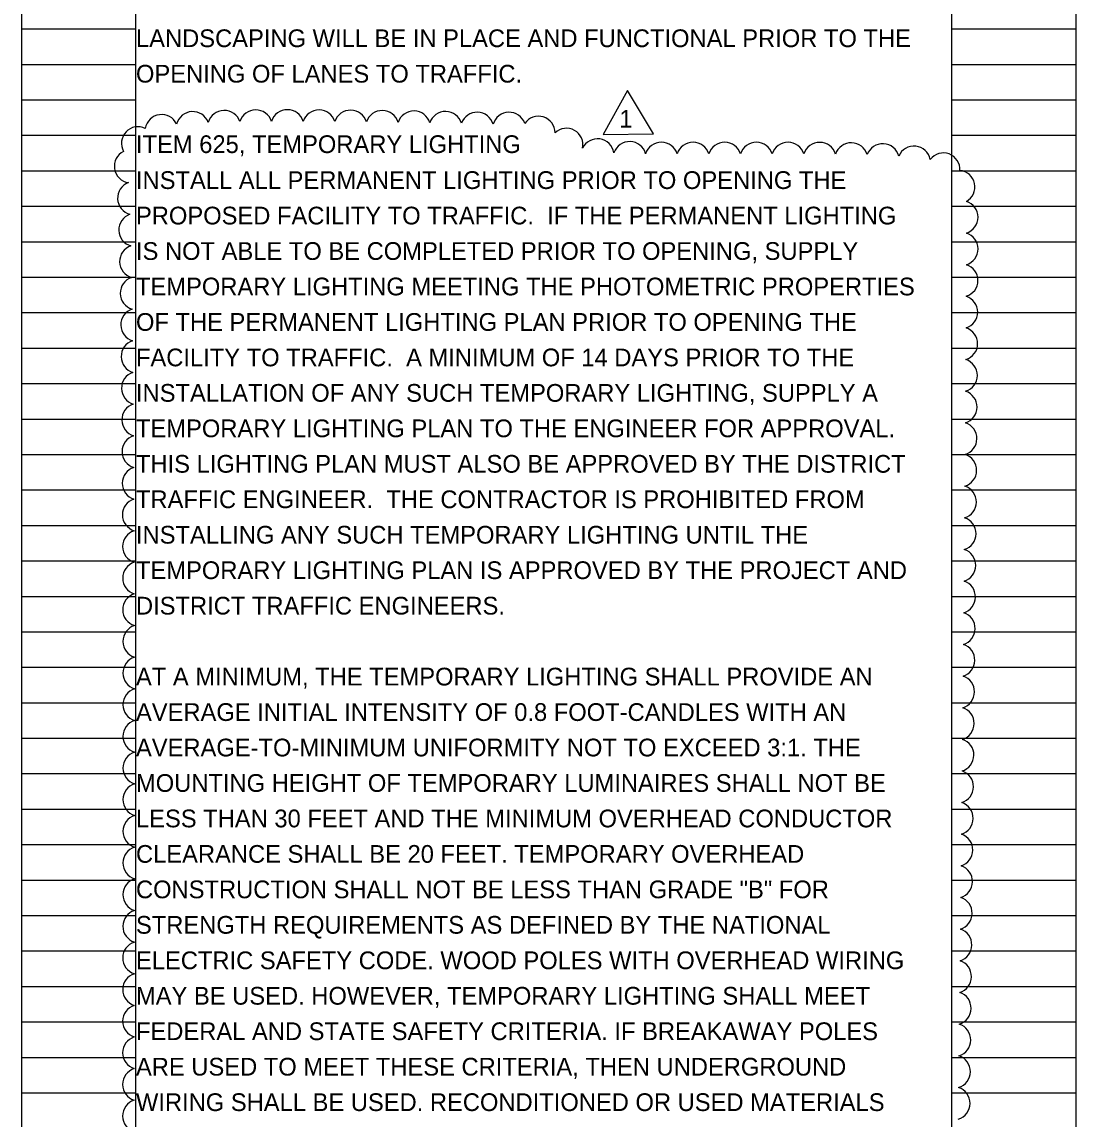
# Model space of a CAD drawing. Extents: x -9 to 32, y -122 to 20.
# Drawn here: x 1.22 to 9.54, y -94.82 to -86.16 of the extents above; entities that cross this region are included whole.
import ezdxf

# ---------------------------------------------------------------- set-up
doc = ezdxf.new("R2010")
doc.units = 0
for name, color, linetype in [('SC_Scratch1', 7, 'Continuous'), ('SC_Scratch2', 7, 'Continuous'), ('SH_Text', 7, 'Continuous')]:
    doc.layers.add(name, color=color, linetype=linetype)

msp = doc.modelspace()

# ---------------------------------------------------------------- linework, layer by layer
at = {"layer": 'SC_Scratch1'}
for p, q in [((1.2158, -100.4944), (1.2158, -80.3344)), ((2.1158, -100.4944), (2.1158, -80.3344)), ((8.5558, -100.4944), (8.5558, -80.3344)), ((9.5358, -100.4944), (9.5358, -80.3344)), ((1.2158, -86.2144), (2.1158, -86.2144)), ((8.5558, -86.2144), (9.5358, -86.2144)), ((1.2158, -86.4944), (2.1158, -86.4944)), ((8.5558, -86.4944), (9.5358, -86.4944)), ((1.2158, -86.7744), (2.1158, -86.7744)), ((8.5558, -86.7744), (9.5358, -86.7744)), ((1.2158, -87.0544), (2.1158, -87.0544)), ((8.5558, -87.0544), (9.5358, -87.0544)), ((1.2158, -87.3344), (2.1158, -87.3344)), ((8.5558, -87.3344), (9.5358, -87.3344)), ((1.2158, -87.6144), (2.1158, -87.6144)), ((8.5558, -87.6144), (9.5358, -87.6144)), ((1.2158, -87.8944), (2.1158, -87.8944)), ((8.5558, -87.8944), (9.5358, -87.8944)), ((1.2158, -88.1744), (2.1158, -88.1744)), ((8.5558, -88.1744), (9.5358, -88.1744)), ((1.2158, -88.4544), (2.1158, -88.4544)), ((8.5558, -88.4544), (9.5358, -88.4544)), ((1.2158, -88.7344), (2.1158, -88.7344)), ((8.5558, -88.7344), (9.5358, -88.7344)), ((1.2158, -89.0144), (2.1158, -89.0144)), ((8.5558, -89.0144), (9.5358, -89.0144)), ((1.2158, -89.2944), (2.1158, -89.2944)), ((8.5558, -89.2944), (9.5358, -89.2944)), ((1.2158, -89.5744), (2.1158, -89.5744)), ((8.5558, -89.5744), (9.5358, -89.5744)), ((1.2158, -89.8544), (2.1158, -89.8544)), ((8.5558, -89.8544), (9.5358, -89.8544)), ((1.2158, -90.1344), (2.1158, -90.1344)), ((8.5558, -90.1344), (9.5358, -90.1344)), ((1.2158, -90.4144), (2.1158, -90.4144)), ((8.5558, -90.4144), (9.5358, -90.4144)), ((1.2158, -90.6944), (2.1158, -90.6944)), ((8.5558, -90.6944), (9.5358, -90.6944)), ((1.2158, -90.9744), (2.1158, -90.9744)), ((8.5558, -90.9744), (9.5358, -90.9744)), ((1.2158, -91.2544), (2.1158, -91.2544)), ((8.5558, -91.2544), (9.5358, -91.2544)), ((1.2158, -91.5344), (2.1158, -91.5344)), ((8.5558, -91.5344), (9.5358, -91.5344)), ((1.2158, -91.8144), (2.1158, -91.8144)), ((8.5558, -91.8144), (9.5358, -91.8144)), ((1.2158, -92.0944), (2.1158, -92.0944)), ((8.5558, -92.0944), (9.5358, -92.0944)), ((1.2158, -92.3744), (2.1158, -92.3744)), ((8.5558, -92.3744), (9.5358, -92.3744)), ((1.2158, -92.6544), (2.1158, -92.6544)), ((8.5558, -92.6544), (9.5358, -92.6544)), ((1.2158, -92.9344), (2.1158, -92.9344)), ((8.5558, -92.9344), (9.5358, -92.9344)), ((1.2158, -93.2144), (2.1158, -93.2144)), ((8.5558, -93.2144), (9.5358, -93.2144)), ((1.2158, -93.4944), (2.1158, -93.4944)), ((8.5558, -93.4944), (9.5358, -93.4944)), ((1.2158, -93.7744), (2.1158, -93.7744)), ((8.5558, -93.7744), (9.5358, -93.7744)), ((1.2158, -94.0544), (2.1158, -94.0544)), ((8.5558, -94.0544), (9.5358, -94.0544)), ((1.2158, -94.3344), (2.1158, -94.3344)), ((8.5558, -94.3344), (9.5358, -94.3344)), ((1.2158, -94.6144), (2.1158, -94.6144)), ((8.5558, -94.6144), (9.5358, -94.6144))]:
    msp.add_line(p, q, dxfattribs=at)
at = {"layer": 'SC_Scratch2'}
msp.add_lwpolyline([(6.2006, -87.0424), (5.9964, -86.7002), (5.8021, -87.0481)], close=True, dxfattribs=at)
for centre, start, end in [((2.5637, -86.998), 20.4455, 165.4455), ((2.8123, -86.9886), 18.86685, 163.86685), ((3.0615, -86.9846), 18.00255, 163.00255), ((3.311, -86.9836), 17.43638, 162.43638), ((3.5605, -86.9848), 17.03423, 162.03423), ((3.8103, -86.9871), 16.88909, 161.88909), ((4.0601, -86.9899), 16.82218, 161.82218), ((4.3098, -86.9931), 16.71835, 161.71835), ((4.5595, -86.9969), 16.52149, 161.52149), ((4.8087, -87.0029), 15.70912, 160.70912), ((5.0608, -87.0034), 19.08461, 164.08461), ((2.3186, -87.0212), 25.38435, 170.38435), ((5.2924, -87.035), 0.39202, 145.39202), ((2.1325, -87.1173), 64.21042, 209.21042), ((5.513, -87.1296), 348.16889, 133.16889), ((5.7593, -87.213), 9.40906, 154.40906), ((6.0121, -87.2352), 15.57736, 160.57736), ((6.2631, -87.2396), 17.41813, 162.41813), ((6.513, -87.2399), 17.44081, 162.44081), ((6.7628, -87.2401), 17.4602, 162.4602), ((7.0127, -87.2402), 17.47705, 162.47705), ((7.2626, -87.2403), 17.49187, 162.49187), ((7.5122, -87.2409), 17.22463, 162.22463), ((7.7615, -87.244), 16.35388, 161.35388), ((8.0102, -87.2522), 14.89346, 159.89346), ((8.2569, -87.2706), 11.57109, 156.57109), ((2.0761, -87.2987), 116.25108, 261.25108), ((8.4886, -87.3247), 357.11236, 142.11236), ((8.6061, -87.4616), 299.13642, 84.13642), ((2.1015, -87.551), 110.2455, 255.2455), ((8.6309, -87.7011), 287.68709, 72.68709), ((2.1113, -87.8014), 109.24305, 254.24305), ((8.6311, -87.9508), 287.39789, 72.39789), ((2.1179, -88.0514), 108.785, 253.785), ((8.6303, -88.2005), 287.26544, 72.26544), ((2.1229, -88.3014), 108.50661, 253.50661), ((8.6291, -88.4503), 287.18486, 72.18486), ((2.1269, -88.5514), 108.3143, 253.3143), ((8.6276, -88.7001), 287.12917, 72.12917), ((2.1301, -88.8013), 108.17116, 253.17116), ((8.6259, -88.9499), 287.0877, 72.0877), ((2.1328, -89.0512), 108.05924, 253.05924), ((8.624, -89.1998), 287.05526, 72.05526), ((2.135, -89.3011), 107.96862, 252.96862), ((8.6221, -89.4496), 287.02899, 72.02899), ((2.1369, -89.551), 107.89329, 252.89329), ((8.62, -89.6994), 287.00715, 72.00715), ((2.1385, -89.8009), 107.82939, 252.82939), ((8.6178, -89.9492), 286.98862, 71.98862), ((2.1398, -90.0508), 107.77428, 252.77428), ((8.6155, -90.1991), 286.97264, 71.97264), ((2.1409, -90.3007), 107.72612, 252.72612), ((8.6132, -90.4489), 286.95867, 71.95867), ((2.1418, -90.5505), 107.68356, 252.68356), ((8.6108, -90.6987), 286.94632, 71.94632), ((2.1425, -90.8004), 107.64559, 252.64559), ((8.6083, -90.9486), 286.93531, 71.93531), ((2.1431, -91.0503), 107.61144, 252.61144), ((8.6059, -91.1984), 286.9254, 71.9254), ((2.1435, -91.3002), 107.58052, 252.58052), ((8.6033, -91.4482), 286.91643, 71.91643), ((2.1438, -91.55), 107.55233, 252.55233), ((8.6008, -91.698), 286.90825, 71.90825), ((2.144, -91.7999), 107.52651, 252.52651), ((8.5982, -91.9479), 286.90076, 71.90076), ((2.144, -92.0498), 107.50274, 252.50274), ((8.5955, -92.1977), 286.89386, 71.89386), ((2.144, -92.2996), 107.48075, 252.48075), ((8.5929, -92.4475), 286.88748, 71.88748), ((2.1439, -92.5495), 107.46035, 252.46035), ((8.5902, -92.6974), 286.88156, 71.88156), ((2.1436, -92.7994), 107.44134, 252.44134), ((8.5875, -92.9472), 286.87604, 71.87604), ((2.1433, -93.0492), 107.42358, 252.42358), ((8.5848, -93.197), 286.87089, 71.87089), ((2.143, -93.2991), 107.40693, 252.40693), ((8.582, -93.4469), 286.86671, 71.86671), ((2.1425, -93.5489), 107.39128, 252.39128), ((8.5792, -93.6967), 286.86692, 71.86692), ((2.1421, -93.7988), 107.38559, 252.38559), ((8.5765, -93.9465), 286.86794, 71.86794), ((2.1416, -94.0486), 107.39971, 252.39971), ((8.5737, -94.1964), 286.86903, 71.86903), ((2.1412, -94.2985), 107.41537, 252.41537), ((8.571, -94.4462), 286.8702, 71.8702), ((2.1408, -94.5483), 107.43211, 252.43211), ((8.5682, -94.696), 286.87145, 71.87145), ((2.1406, -94.7981), 107.45003, 252.45003)]:
    msp.add_arc(centre, 0.131, start, end, dxfattribs=at)

# ---------------------------------------------------------------- texts
msp.add_text('1', height=0.14, dxfattribs=at).set_placement((5.931, -86.9942))
at = {"layer": 'SH_Text'}
for s, p in [('LANDSCAPING WILL BE IN PLACE AND FUNCTIONAL PRIOR TO THE ', (2.1158, -86.3581)), ('OPENING OF LANES TO TRAFFIC.', (2.1158, -86.6381)), ('ITEM 625, TEMPORARY LIGHTING', (2.1158, -87.1944)), ('INSTALL ALL PERMANENT LIGHTING PRIOR TO OPENING THE ', (2.1158, -87.4781)), ('PROPOSED FACILITY TO TRAFFIC.  IF THE PERMANENT LIGHTING ', (2.1158, -87.7581)), ('IS NOT ABLE TO BE COMPLETED PRIOR TO OPENING, SUPPLY ', (2.1158, -88.0381)), ('TEMPORARY LIGHTING MEETING THE PHOTOMETRIC PROPERTIES ', (2.1158, -88.3181)), ('OF THE PERMANENT LIGHTING PLAN PRIOR TO OPENING THE ', (2.1158, -88.5981)), ('FACILITY TO TRAFFIC.  A MINIMUM OF 14 DAYS PRIOR TO THE ', (2.1158, -88.8781)), ('INSTALLATION OF ANY SUCH TEMPORARY LIGHTING, SUPPLY A ', (2.1158, -89.1581)), ('TEMPORARY LIGHTING PLAN TO THE ENGINEER FOR APPROVAL.  ', (2.1158, -89.4381)), ('THIS LIGHTING PLAN MUST ALSO BE APPROVED BY THE DISTRICT ', (2.1158, -89.7181)), ('TRAFFIC ENGINEER.  THE CONTRACTOR IS PROHIBITED FROM ', (2.1158, -89.9981)), ('INSTALLING ANY SUCH TEMPORARY LIGHTING UNTIL THE ', (2.1158, -90.2781)), ('TEMPORARY LIGHTING PLAN IS APPROVED BY THE PROJECT AND ', (2.1158, -90.5581)), ('DISTRICT TRAFFIC ENGINEERS.', (2.1158, -90.8381)), ('AT A MINIMUM, THE TEMPORARY LIGHTING SHALL PROVIDE AN ', (2.1158, -91.3981)), ('AVERAGE INITIAL INTENSITY OF 0.8 FOOT-CANDLES WITH AN ', (2.1158, -91.6781)), ('AVERAGE-TO-MINIMUM UNIFORMITY NOT TO EXCEED 3:1. THE ', (2.1158, -91.9581)), ('MOUNTING HEIGHT OF TEMPORARY LUMINAIRES SHALL NOT BE ', (2.1158, -92.2381)), ('LESS THAN 30 FEET AND THE MINIMUM OVERHEAD CONDUCTOR ', (2.1158, -92.5181)), ('CLEARANCE SHALL BE 20 FEET. TEMPORARY OVERHEAD ', (2.1158, -92.7981)), ('CONSTRUCTION SHALL NOT BE LESS THAN GRADE "B" FOR ', (2.1158, -93.0781)), ('STRENGTH REQUIREMENTS AS DEFINED BY THE NATIONAL ', (2.1158, -93.3581)), ('ELECTRIC SAFETY CODE. WOOD POLES WITH OVERHEAD WIRING ', (2.1158, -93.6381)), ('MAY BE USED. HOWEVER, TEMPORARY LIGHTING SHALL MEET ', (2.1158, -93.9181)), ('FEDERAL AND STATE SAFETY CRITERIA. IF BREAKAWAY POLES ', (2.1158, -94.1981)), ('ARE USED TO MEET THESE CRITERIA, THEN UNDERGROUND ', (2.1158, -94.4781)), ('WIRING SHALL BE USED. RECONDITIONED OR USED MATERIALS ', (2.1158, -94.7581))]:
    msp.add_text(s, height=0.14, dxfattribs=at).set_placement(p)

doc.saveas('drawing.dxf')
